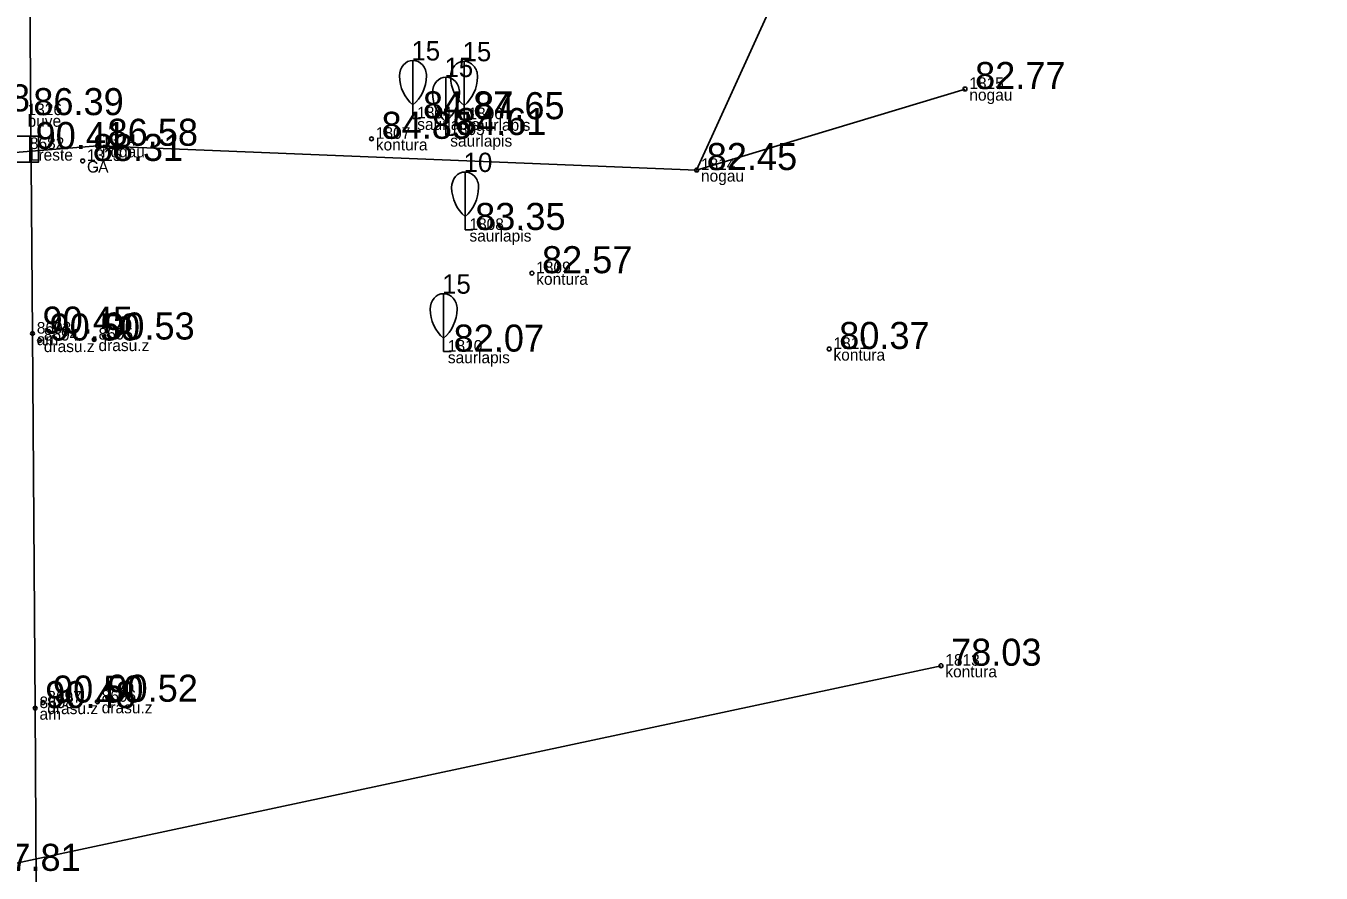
# Model space of a CAD drawing. Extents: x 614911 to 615803, y 262110 to 264311.
# Drawn here: x 615636.42 to 615669.97, y 263407.32 to 263429.25 of the extents above; entities that cross this region are included whole.
import ezdxf

# ---------------------------------------------------------------- set-up
doc = ezdxf.new("R2010")
doc.units = 0
for name, color, linetype in [('Level 1', 7, 'Continuous'), ('Level 31', 7, 'Continuous'), ('Level 37', 7, 'Continuous'), ('Level 48', 7, 'Continuous'), ('Level 53', 7, 'Continuous'), ('Level 54', 7, 'Continuous'), ('Level 57', 7, 'Continuous'), ('Level 58', 7, 'Continuous')]:
    doc.layers.add(name, color=color, linetype=linetype)

msp = doc.modelspace()

# ---------------------------------------------------------------- linework, layer by layer
at = {"layer": 'Level 1'}
for p, q in [((615646.447, 263427.212), (615646.447, 263426.86)), ((615647.772, 263427.191), (615647.772, 263426.839)), ((615646.447, 263426.86), (615646.647, 263426.86)), ((615647.302, 263426.781), (615647.302, 263426.429)), ((615647.772, 263426.839), (615647.972, 263426.839)), ((615647.302, 263426.429), (615647.502, 263426.429)), ((615647.799, 263424.324), (615647.799, 263423.972)), ((615647.799, 263423.972), (615647.999, 263423.972)), ((615647.241, 263421.174), (615647.241, 263420.822)), ((615647.241, 263420.822), (615647.441, 263420.822))]:
    msp.add_line(p, q, dxfattribs=at)
for points in [[(615646.447, 263428.36), (615646.447, 263427.212)], [(615647.772, 263428.339), (615647.772, 263427.191)], [(615647.302, 263427.929), (615647.302, 263426.781)], [(615647.799, 263425.472), (615647.799, 263424.324)], [(615647.241, 263422.322), (615647.241, 263421.174)]]:
    msp.add_lwpolyline(points, dxfattribs=at)
for centre, major_axis, start_param, end_param in [((615646.447, 263427.96), (0, 0.4), 0, 1.570796), ((615646.447, 263427.96), (0, -0.4), 1.570796, 3.141593), ((615647.772, 263427.939), (0, 0.4), 0, 1.570796), ((615647.772, 263427.939), (0, -0.4), 1.570796, 3.141593), ((615646.922, 263427.983), (0, -0.943), 4.7372, 5.669711), ((615645.972, 263427.983), (0, -0.943), 0.613474, 1.545985), ((615647.302, 263427.529), (0, 0.4), 0, 1.570796), ((615647.302, 263427.529), (0, -0.4), 1.570796, 3.141593), ((615648.247, 263427.962), (0, -0.943), 4.7372, 5.669711), ((615647.297, 263427.962), (0, -0.943), 0.613474, 1.545985), ((615647.777, 263427.552), (0, -0.943), 4.7372, 5.669711), ((615646.827, 263427.552), (0, -0.943), 0.613474, 1.545985), ((615647.799, 263425.072), (0, 0.4), 0, 1.570796), ((615647.799, 263425.072), (0, -0.4), 1.570796, 3.141593), ((615648.274, 263425.095), (0, -0.943), 4.7372, 5.669711), ((615647.324, 263425.095), (0, -0.943), 0.613474, 1.545985), ((615647.241, 263421.922), (0, 0.4), 0, 1.570796), ((615647.241, 263421.922), (0, -0.4), 1.570796, 3.141593), ((615647.716, 263421.945), (0, -0.943), 4.7372, 5.669711), ((615646.766, 263421.945), (0, -0.943), 0.613474, 1.545985)]:
    msp.add_ellipse(centre, major_axis=major_axis, ratio=0.875, start_param=start_param, end_param=end_param, dxfattribs=at)
at = {"layer": 'Level 31'}
for points in [[(615669.966, 263449.096), (615658.187, 263435.178), (615653.795, 263425.523)], [(615607.219, 263423.823), (615618.278, 263424.383), (615627.676, 263425.297), (615638.279, 263426.151), (615653.795, 263425.523), (615660.745, 263427.62)], [(615602.604, 263410.766), (615623.401, 263410.099), (615635.242, 263407.38), (615660.123, 263412.69)]]:
    msp.add_lwpolyline(points, dxfattribs=at)
at = {"layer": 'Level 37'}
msp.add_lwpolyline([(615636.517, 263431.183), (615636.595, 263421.289), (615636.665, 263411.593), (615636.806, 263386.87), (615636.931, 263375.725), (615636.948, 263365.501), (615637.059, 263355.344), (615637.134, 263343.807), (615637.167, 263335.039), (615637.241, 263325.081), (615637.336, 263313.942), (615637.374, 263306.112), (615637.482, 263292.409), (615637.574, 263278.5), (615637.654, 263266.567), (615637.756, 263250.366), (615637.867, 263239.792), (615637.928, 263229.314), (615638.03, 263218.463), (615638.11, 263207.891), (615638.19, 263197.069), (615638.393, 263173.174)], dxfattribs=at)
at = {"layer": 'Level 48'}
msp.add_line((615636.527, 263426.404), (615636.527, 263425.729), dxfattribs=at)
msp.add_lwpolyline([(615636.077, 263426.404), (615636.752, 263426.404), (615636.752, 263425.729), (615636.077, 263425.729)], close=True, dxfattribs=at)
at = {"layer": 'Level 57'}
for centre in [(615660.745, 263427.62), (615638.279, 263426.151), (615645.375, 263426.331), (615637.895, 263425.758), (615653.795, 263425.523), (615649.529, 263422.852), (615636.595, 263421.289), (615636.777, 263421.109), (615638.193, 263421.135), (615657.226, 263420.89), (615660.123, 263412.69), (615636.867, 263411.737), (615638.276, 263411.758), (615636.665, 263411.593)]:
    msp.add_circle(centre, 0.05, dxfattribs=at)
at = {"layer": 'Level 58'}
for centre in [(615660.745, 263427.62), (615638.279, 263426.151), (615645.375, 263426.331), (615637.895, 263425.758), (615653.795, 263425.523), (615649.529, 263422.852), (615636.595, 263421.289), (615636.777, 263421.109), (615638.193, 263421.135), (615657.226, 263420.89), (615660.123, 263412.69), (615636.867, 263411.737), (615638.276, 263411.758), (615636.665, 263411.593)]:
    msp.add_circle(centre, 0.05, dxfattribs=at)

# ---------------------------------------------------------------- texts
at = {"layer": 'Level 1'}
for s, p in [(' 15', (615646.222, 263428.36)), (' 15', (615647.547, 263428.339)), (' 15', (615647.077, 263427.929)), (' 10', (615647.574, 263425.472)), (' 15', (615647.016, 263422.322))]:
    msp.add_text(s, height=0.5, dxfattribs=at).set_placement(p)
at = {"layer": 'Level 48'}
msp.add_text(' 90.41', height=0.7, dxfattribs=at).set_placement((615636.415, 263426.066))
at = {"layer": 'Level 53'}
for s, p in [(' nogau', (615660.745, 263427.32)), (' buve', (615636.356, 263426.644)), (' saurlapis', (615646.447, 263426.56)), (' saurlapis', (615647.772, 263426.539)), (' saurlapis', (615647.302, 263426.129)), (' kontura', (615645.375, 263426.031)), (' Lreste', (615636.415, 263425.766)), (' G', (615637.895, 263425.458)), (' CA', (615637.895, 263425.458)), (' nogau', (615638.279, 263425.851)), (' nogau', (615653.795, 263425.223)), (' saurlapis', (615647.799, 263423.672)), (' kontura', (615649.529, 263422.552)), (' am', (615636.595, 263420.989)), (' drasu.z', (615636.777, 263420.809)), (' drasu.z', (615638.193, 263420.835)), (' saurlapis', (615647.241, 263420.522)), (' kontura', (615657.226, 263420.59)), (' kontura', (615660.123, 263412.39)), (' drasu.z', (615636.867, 263411.437)), (' drasu.z', (615638.276, 263411.458)), (' am', (615636.665, 263411.293))]:
    msp.add_text(s, height=0.3, dxfattribs=at).set_placement(p)
at = {"layer": 'Level 54'}
for s, p in [(' 1815', (615660.745, 263427.62)), (' 1326', (615636.356, 263426.944)), (' 1804', (615646.447, 263426.86)), (' 1806', (615647.772, 263426.839)), (' 1324', (615638.279, 263426.151)), (' 1807', (615645.375, 263426.331)), (' 1805', (615647.302, 263426.429)), (' 8682', (615636.415, 263426.066)), (' 1325', (615637.895, 263425.758)), (' 1814', (615653.795, 263425.523)), (' 1808', (615647.799, 263423.972)), (' 1809', (615649.529, 263422.852)), (' 8693', (615636.595, 263421.289)), (' 8694', (615636.777, 263421.109)), (' 8695', (615638.193, 263421.135)), (' 1810', (615647.241, 263420.822)), (' 1811', (615657.226, 263420.89)), (' 1813', (615660.123, 263412.69)), (' 8697', (615636.867, 263411.737)), (' 8696', (615638.276, 263411.758)), (' 8698', (615636.665, 263411.593))]:
    msp.add_text(s, height=0.3, dxfattribs=at).set_placement(p)
at = {"layer": 'Level 58'}
for s, p in [(' 82.77', (615660.745, 263427.62)), (' 86.08', (615633.929, 263427.04)), (' 86.39', (615636.356, 263426.944)), (' 84.87', (615646.447, 263426.86)), (' 84.65', (615647.772, 263426.839)), (' 84.61', (615647.302, 263426.429)), (' 86.58', (615638.279, 263426.151)), (' 84.85', (615645.375, 263426.331)), (' 88.31', (615637.895, 263425.758)), (' 82.45', (615653.795, 263425.523)), (' 83.35', (615647.799, 263423.972)), (' 82.57', (615649.529, 263422.852)), (' 90.45', (615636.595, 263421.289)), (' 90.50', (615636.777, 263421.109)), (' 90.53', (615638.193, 263421.135)), (' 82.07', (615647.241, 263420.822)), (' 80.37', (615657.226, 263420.89)), (' 78.03', (615660.123, 263412.69)), (' 90.50', (615636.867, 263411.737)), (' 90.52', (615638.276, 263411.758)), (' 90.48', (615636.665, 263411.593)), (' 77.81', (615635.242, 263407.38))]:
    msp.add_text(s, height=0.7, dxfattribs=at).set_placement(p)

doc.saveas('drawing.dxf')
